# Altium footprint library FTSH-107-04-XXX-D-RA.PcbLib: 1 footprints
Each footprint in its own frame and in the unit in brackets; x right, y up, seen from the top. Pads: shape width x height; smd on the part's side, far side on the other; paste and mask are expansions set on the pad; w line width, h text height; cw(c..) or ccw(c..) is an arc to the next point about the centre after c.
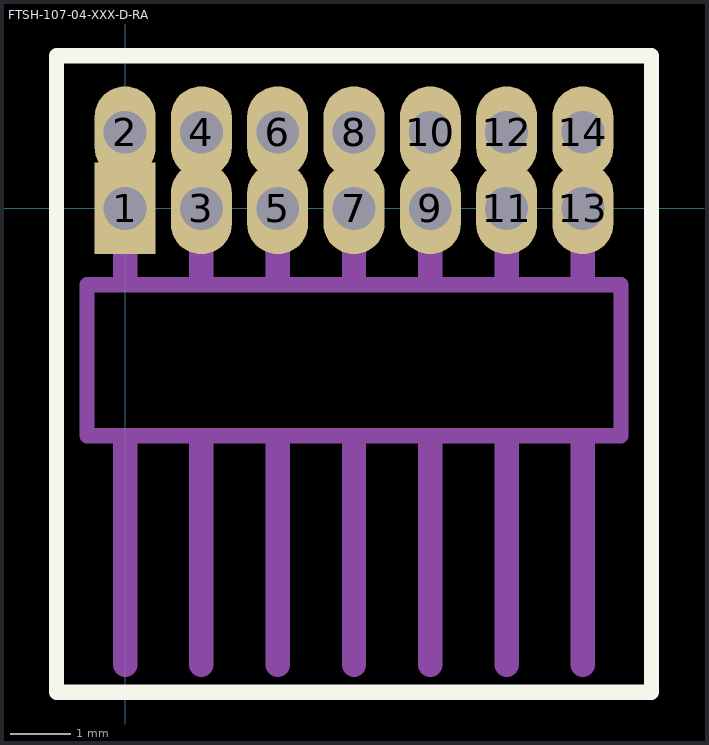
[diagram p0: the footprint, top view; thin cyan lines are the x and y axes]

## FTSH-107-04-XXX-D-RA [mil]
pads (14):
  rect 40x60 / inner round 40 / far side rect 40x60 hole 28 mask+2: 1(0,0)
  oval 40x60 / inner round 40 / far side oval 40x60 hole 28 mask+2: 2(0,50) 3(50,0) 4(50,50) 5(100,0) 6(100,50) 7(150,0) 8(150,50) 9(200,0) 10(200,50) 11(250,0) 12(250,50) 13(300,0) 14(300,50)
Top Overlay:
  lines w10: -45,-317 -45,100 345,100 345,-317 -45,-317
Mechanical 1:
  lines w10: -25,-149 -25,-50 325,-50 325,-149 -25,-149
  lines w16: 0,-299 0,-154 ; 0,-45 0,50 ; 50,-299 50,-154 ; 50,-45 50,50 ; 100,-299 100,-154 ; 100,-45 100,50 ; 150,-299 150,-154 ; 150,-45 150,50 ; 200,-299 200,-154 ; 200,-45 200,50 ; 250,-299 250,-154 ; 250,-45 250,50 ; 300,-299 300,-154 ; 300,-45 300,50
  text "J1" at 132.43,-118 h30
